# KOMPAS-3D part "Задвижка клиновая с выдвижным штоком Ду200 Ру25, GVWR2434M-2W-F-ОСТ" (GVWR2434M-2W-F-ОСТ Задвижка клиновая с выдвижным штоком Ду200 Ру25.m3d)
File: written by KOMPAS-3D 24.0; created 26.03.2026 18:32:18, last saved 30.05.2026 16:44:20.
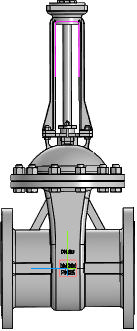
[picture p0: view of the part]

Document properties: Автор: R2D2; Полное имя файла: E:\Работа\Зайцев\GVWR2434M-2W-F-ОСТ Задвижка клиновая с выдвижным штоком DN.ru Ду50-300 Ру25\исходные материалы\DN200\GVWR2434M-2W-F-ОСТ Задвижка клиновая с выдвижным штоком Ду200 Ру25.m3d

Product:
- Component [detail]: AS 1110 - M10 x 35  | qty 4  | pos. 2  | Комментарий: Болты и винты   шестигранные точные   метрические ISO; Автор: R2D2; additional columns: Сталь, мягкая; source file: AS 1110 - M10 x 35 AS 1110 - M10 x 35.m3d
- Component [detail]: ANSI B18.2.4.2M - M10x1,5 - 16  | designation ANSI B18.2.4.2M - M10x1,5  | qty 4  | pos. 3  | Комментарий: Типы метрических   шестигранных гаек   2; Автор: R2D2; additional columns: Сталь, мягкая; source file: ANSI B18.2.4.2M - M10x1,5 ANSI B18.2.4.2M - M10x1,5 - 16.m3d
- Component [detail]: ANSI B18.2.4.2M - M8x1,25 - 13  | designation ANSI B18.2.4.2M - M8x1,25  | qty 1  | pos. 4  | Комментарий: Типы метрических   шестигранных гаек   2; Автор: R2D2; additional columns: Сталь, мягкая; source file: ANSI B18.2.4.2M - M8x1,25 ANSI B18.2.4.2M - M8x1,25 - 13.m3d
- Component [detail]: ANSI B18.2.4.2M - M20x2,5 - 30  | designation ANSI B18.2.4.2M - M20x2,5  | qty 12  | pos. 5  | Комментарий: Типы метрических   шестигранных гаек   2; Автор: R2D2; additional columns: Сталь, мягкая; source file: ANSI B18.2.4.2M - M20x2,5 ANSI B18.2.4.2M - M20x2,5 - 30.m3d
- Component [detail]: AS 1110 - M20 x 70  | qty 12  | pos. 6  | Комментарий: Болты и винты   шестигранные точные   метрические ISO; Автор: R2D2; additional columns: Сталь, мягкая; source file: AS 1110 - M20 x 70 AS 1110 - M20 x 70.m3d
- Component [detail]: Деталь1  | qty 1  | pos. 7  | Автор: R2D2; additional columns: Типовые; source file: 2.m3d
- Component [detail]: ANSI B18.2.4.2M - M8x1,25 - 13  | designation ANSI B18.2.4.2M - M8x1,25-01  | qty 1  | pos. 8  | Комментарий: Типы метрических   шестигранных гаек   2; Автор: R2D2; additional columns: Сталь, мягкая; source file: ANSI B18.2.4.2M - M8x1,25 ANSI B18.2.4.2M - M8x1,25 - 13.m3d
- Component [detail]: Фланец  | qty 2  | pos. 7  | Автор: R2D2; additional columns: Типовые; source file: Фланец DN200 Pn25 b34.m3d
- Component [detail]: Деталь1  | qty 1  | pos. 9  | Автор: R2D2; additional columns: Типовые; source file: Фланец Б.m3d
- Body: Тело 1  | qty 1
    Масса: 185.229931
- Body: Тело 2  | qty 1
    Масса: 185.229931
- Part/product: Задвижка клиновая с выдвижным штоком Ду200 Ру25  | designation GVWR2434M-2W-F-ОСТ
    Масса: 100
    Раздел спецификации: Прочие изделия
    Примечание: D040-07590

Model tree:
1. Массив по концентрической сетке:1  (labels: Грань.Твердое тело1)  (12 pattern instances)
     Шаг 2 = 360
2. Массив по сетке:1  (labels: Грань.Твердое тело1)  (4 pattern instances)
     Шаг 1 = 50; Угол раствора = 90; Шаг 2 = 120
3. Масштабирование:1
4. Масштабирование : Твердое тело1
5. Масштабирование : Solid1
6. Масштабирование : Ребро.Solid1  (with: Масштабирование : Solid1)  (labels: Твердое тело1; Solid1; Ребро.Solid1)
     Масштаб по оси Х = 1; Масштаб по оси Y = 1; Масштаб по оси Z = 1; Коэффициент = 1.25
7. Элемент выдавливания:1  (with: Грань.Элемент выдавливания:2, Грань.Элемент вращения:1)
     Расстояние 1 = 33.5965
8. Элемент выдавливания:2  (with: Грань.Элемент выдавливания:1, Грань.Элемент вращения:1)
     Расстояние 1 = 40.4417
9. Скругление:1  (with: Ребро.Элемент выдавливания:2, Ребро.Элемент выдавливания:1)
     Радиус = 10
10. Элемент выдавливания:3  (with: Грань.Элемент выдавливания:1)
     Расстояние 1 = 70
11. Эскиз:1  (with: Вершина.Элемент выдавливания:3)
12. Элемент выдавливания:4  (with: Грань.Элемент выдавливания:1, Грань.Элемент выдавливания:4)
     Расстояние 1 = 291.906
13. Эскиз:2
14. Элемент выдавливания:5  (with: Грань.Элемент выдавливания:1)
     Расстояние 1 = 126; Смещение 1 = 1
15. Элемент по траектории:2  (with: Грань.Элемент выдавливания:3, Грань.Элемент вращения:1)  (labels: Грань.Твердое тело1; Грань.Solid1; Solid1; Твердое тело1)
     Длина траектории = 397.552; Ориентация = 2; Расстояние = -200; Ориентация = 2; Расстояние = -800

Referenced files in E:\Работа\Зайцев\GVWR2434M-2W-F-ОСТ Задвижка клиновая с выдвижным штоком DN.ru Ду50-300 Ру25\исходные материалы\DN200\: AS 1110 - M10 x 35 AS 1110 - M10 x 35.m3d, ANSI B18.2.4.2M - M10x1,5 ANSI B18.2.4.2M - M10x1,5 - 16.m3d, ANSI B18.2.4.2M - M8x1,25 ANSI B18.2.4.2M - M8x1,25 - 13.m3d, ANSI B18.2.4.2M - M20x2,5 ANSI B18.2.4.2M - M20x2,5 - 30.m3d, AS 1110 - M20 x 70 AS 1110 - M20 x 70.m3d, 2.m3d, Фланец Б.m3d, Фланец DN200 Pn25 b34.m3d
Referenced files in E:\Работа\Зайцев\GVWR3131M-2W-F-S Задвижка клиновая с выдвижным штоком DN.ru Ду50-200 Ру63\DN200\исходные материалы\: ANSI B18.2.4.2M - M20x2,5 ANSI B18.2.4.2M - M20x2,5 - 30.m3d, AS 1110 - M20 x 70 AS 1110 - M20 x 70.m3d, ANSI B18.2.4.2M - M10x1,5 ANSI B18.2.4.2M - M10x1,5 - 16.m3d, AS 1110 - M10 x 35 AS 1110 - M10 x 35.m3d
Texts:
  GVWR2434M-2W-F-ОСТ
  DN200
  GOST 26.020 Pr3
  PN25
  AS 1110 - M10 x 35 AS 1110 - M10 x 35 (1)
  ANSI B18.2.4.2M - M10x1,5 ANSI B18.2.4.2M - M10x1,5 - 16 (1)
  ANSI B18.2.4.2M - M8x1,25 ANSI B18.2.4.2M - M8x1,25 - 13
  ANSI B18.2.4.2M - M20x2,5 ANSI B18.2.4.2M - M20x2,5 - 30 (1)
  AS 1110 - M20 x 70 AS 1110 - M20 x 70 (1)
  Деталь1 Деталь1
  ANSI B18.2.4.2M - M20x2,5 ANSI B18.2.4.2M - M20x2,5 - 30 (2)
  AS 1110 - M20 x 70 AS 1110 - M20 x 70 (2)
  ANSI B18.2.4.2M - M20x2,5 ANSI B18.2.4.2M - M20x2,5 - 30 (3)
  AS 1110 - M20 x 70 AS 1110 - M20 x 70 (3)
  ANSI B18.2.4.2M - M20x2,5 ANSI B18.2.4.2M - M20x2,5 - 30 (4)
  AS 1110 - M20 x 70 AS 1110 - M20 x 70 (4)
  ANSI B18.2.4.2M - M20x2,5 ANSI B18.2.4.2M - M20x2,5 - 30 (5)
  AS 1110 - M20 x 70 AS 1110 - M20 x 70 (5)
  ANSI B18.2.4.2M - M20x2,5 ANSI B18.2.4.2M - M20x2,5 - 30 (6)
  AS 1110 - M20 x 70 AS 1110 - M20 x 70 (6)
  ANSI B18.2.4.2M - M20x2,5 ANSI B18.2.4.2M - M20x2,5 - 30 (7)
  AS 1110 - M20 x 70 AS 1110 - M20 x 70 (7)
  ANSI B18.2.4.2M - M20x2,5 ANSI B18.2.4.2M - M20x2,5 - 30 (8)
  AS 1110 - M20 x 70 AS 1110 - M20 x 70 (8)
  ANSI B18.2.4.2M - M20x2,5 ANSI B18.2.4.2M - M20x2,5 - 30 (9)
  AS 1110 - M20 x 70 AS 1110 - M20 x 70 (9)
  ANSI B18.2.4.2M - M20x2,5 ANSI B18.2.4.2M - M20x2,5 - 30 (10)
  AS 1110 - M20 x 70 AS 1110 - M20 x 70 (10)
  ANSI B18.2.4.2M - M20x2,5 ANSI B18.2.4.2M - M20x2,5 - 30 (11)
  AS 1110 - M20 x 70 AS 1110 - M20 x 70 (11)
  ANSI B18.2.4.2M - M20x2,5 ANSI B18.2.4.2M - M20x2,5 - 30 (12)
  AS 1110 - M20 x 70 AS 1110 - M20 x 70 (12)
  ANSI B18.2.4.2M - M10x1,5 ANSI B18.2.4.2M - M10x1,5 - 16 (2)
  AS 1110 - M10 x 35 AS 1110 - M10 x 35 (2)
  ANSI B18.2.4.2M - M10x1,5 ANSI B18.2.4.2M - M10x1,5 - 16 (3)
  AS 1110 - M10 x 35 AS 1110 - M10 x 35 (3)
  ANSI B18.2.4.2M - M10x1,5 ANSI B18.2.4.2M - M10x1,5 - 16 (4)
  AS 1110 - M10 x 35 AS 1110 - M10 x 35 (4)
  ANSI B18.2.4.2M - M8x1,25-01 ANSI B18.2.4.2M - M8x1,25 - 13
  Фланец (1)
  Фланец (2)
  Ось Y.Начало координат
  Ось Z.Начало координат
  Плоскость ZY.Начало координат
  Плоскость ZX.Начало координат
  Плоскость XY.Начало координат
